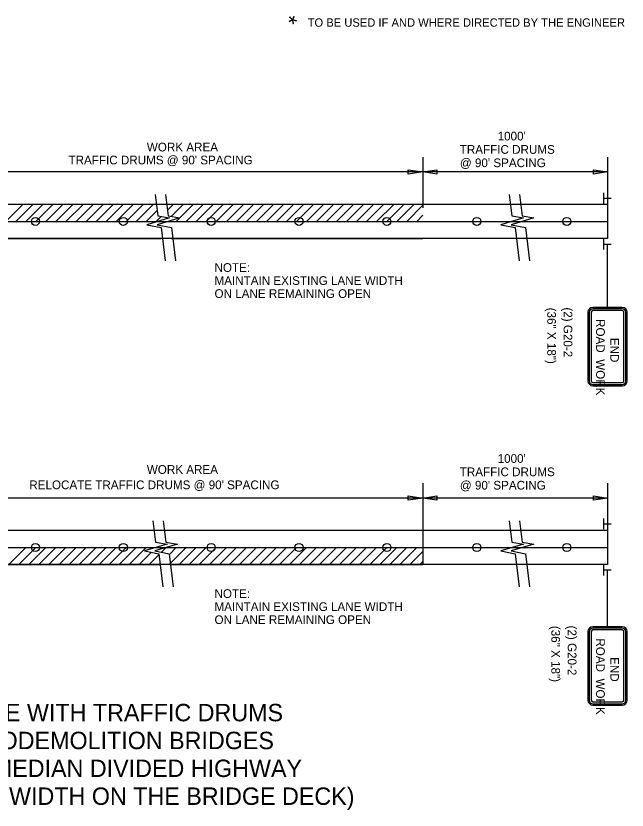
# Model space of a CAD drawing. Extents: x 1930579 to 1938222, y 596452 to 597761.
# Drawn here: x 1937236 to 1937657, y 596554 to 597101 of the extents above; entities that cross this region are included whole.
import ezdxf

# ---------------------------------------------------------------- set-up
doc = ezdxf.new("R2010")
doc.units = 0
for name, color, linetype in [('Default', 7, 'Continuous'), ('P_TC_Signs_Temporary', 7, 'Continuous'), ('R_Border', 7, 'Continuous')]:
    doc.layers.add(name, color=color, linetype=linetype)

msp = doc.modelspace()

# ---------------------------------------------------------------- linework, layer by layer
at = {"layer": 'Default'}
for p, q in [((1937516.16, 597003.98), (1937516.16, 596968.94)), ((1937643.39, 597003.98), (1937643.39, 596947.87)), ((1937506.1, 596992.19), (1937506.1, 596995.2)), ((1937506.1, 596995.2), (1937516.16, 596993.7)), ((1937516.16, 596993.7), (1937525.82, 596995.15)), ((1937525.82, 596995.15), (1937525.82, 596992.25)), ((1937633.73, 596992.25), (1937633.73, 596995.15)), ((1937633.73, 596995.15), (1937643.39, 596993.7)), ((1937516.16, 596993.7), (1937188.67, 596993.7)), ((1937516.16, 596993.7), (1937506.1, 596992.19)), ((1937525.82, 596992.25), (1937516.16, 596993.7)), ((1937643.39, 596993.7), (1937516.16, 596993.7)), ((1937643.39, 596993.7), (1937633.73, 596992.25)), ((1937640.73, 596979.4), (1937640.73, 596971.92)), ((1937640.84, 596975.68), (1937645.95, 596975.68)), ((1937643.39, 596971.31), (1936696.54, 596971.31)), ((1937228.83, 596959.59), (1937240.55, 596971.31)), ((1937235.73, 596959.59), (1937247.45, 596971.31)), ((1937242.64, 596959.59), (1937254.36, 596971.31)), ((1937249.54, 596959.59), (1937261.26, 596971.31)), ((1937256.45, 596959.59), (1937268.17, 596971.31)), ((1937263.35, 596959.59), (1937275.07, 596971.31)), ((1937270.26, 596959.59), (1937281.98, 596971.31)), ((1937277.16, 596959.59), (1937288.88, 596971.31)), ((1937284.07, 596959.59), (1937295.79, 596971.31)), ((1937290.97, 596959.59), (1937302.69, 596971.31)), ((1937297.88, 596959.59), (1937309.6, 596971.31)), ((1937304.79, 596959.59), (1937316.5, 596971.31)), ((1937311.69, 596959.59), (1937323.41, 596971.31)), ((1937318.6, 596959.59), (1937330.31, 596971.31)), ((1937325.5, 596959.59), (1937333.09, 596967.18)), ((1937340.18, 596967.37), (1937344.13, 596971.31)), ((1937342.74, 596963.02), (1937351.03, 596971.31)), ((1937348.61, 596961.98), (1937357.94, 596971.31)), ((1937353.12, 596959.59), (1937364.84, 596971.31)), ((1937360.03, 596959.59), (1937371.75, 596971.31)), ((1937366.93, 596959.59), (1937378.65, 596971.31)), ((1937373.84, 596959.59), (1937385.56, 596971.31)), ((1937380.74, 596959.59), (1937392.46, 596971.31)), ((1937387.65, 596959.59), (1937399.37, 596971.31)), ((1937394.55, 596959.59), (1937406.27, 596971.31)), ((1937401.46, 596959.59), (1937413.18, 596971.31)), ((1937408.37, 596959.59), (1937420.08, 596971.31)), ((1937415.27, 596959.59), (1937426.99, 596971.31)), ((1937422.18, 596959.59), (1937433.89, 596971.31)), ((1937429.08, 596959.59), (1937440.8, 596971.31)), ((1937435.99, 596959.59), (1937447.71, 596971.31)), ((1937442.89, 596959.59), (1937454.61, 596971.31)), ((1937449.8, 596959.59), (1937461.52, 596971.31)), ((1937456.7, 596959.59), (1937468.42, 596971.31)), ((1937463.61, 596959.59), (1937475.33, 596971.31)), ((1937470.51, 596959.59), (1937482.23, 596971.31)), ((1937477.42, 596959.59), (1937489.14, 596971.31)), ((1937484.32, 596959.59), (1937496.04, 596971.31)), ((1937491.23, 596959.59), (1937502.95, 596971.31)), ((1937498.13, 596959.59), (1937509.85, 596971.31)), ((1937505.04, 596959.59), (1937516.16, 596970.71)), ((1937332.41, 596959.59), (1937335.81, 596962.99)), ((1937346.22, 596959.59), (1937348.52, 596961.89)), ((1937511.95, 596959.59), (1937516.16, 596963.8)), ((1936696.54, 596959.59), (1937643.39, 596959.59)), ((1937643.39, 596947.87), (1936696.54, 596947.87)), ((1937188.46, 596947.87), (1937335.53, 596947.87)), ((1937343, 596947.87), (1937516.16, 596947.87)), ((1937640.73, 596947.64), (1937640.73, 596940.16)), ((1937640.84, 596943.92), (1937645.95, 596943.92)), ((1937516.16, 596779.28), (1937516.16, 596723.17)), ((1937516.16, 596779.28), (1937516.16, 596744.24)), ((1937643.39, 596779.28), (1937643.39, 596723.17)), ((1937506.1, 596767.49), (1937506.1, 596770.5)), ((1937506.1, 596770.5), (1937516.16, 596769)), ((1937516.16, 596769), (1937525.82, 596770.45)), ((1937525.82, 596770.45), (1937525.82, 596767.55)), ((1937633.73, 596767.55), (1937633.73, 596770.45)), ((1937633.73, 596770.45), (1937643.39, 596769)), ((1937516.16, 596769), (1937188.67, 596769)), ((1937516.16, 596769), (1937506.1, 596767.49)), ((1937525.82, 596767.55), (1937516.16, 596769)), ((1937643.39, 596769), (1937516.16, 596769)), ((1937643.39, 596769), (1937633.73, 596767.55)), ((1937640.73, 596754.94), (1937640.73, 596747.46)), ((1937640.84, 596751.22), (1937645.95, 596751.22)), ((1937643.39, 596746.61), (1936696.54, 596746.61)), ((1936696.54, 596734.89), (1937643.39, 596734.89)), ((1937230.92, 596723.17), (1937242.64, 596734.89)), ((1937237.82, 596723.17), (1937249.54, 596734.89)), ((1937244.73, 596723.17), (1937256.45, 596734.89)), ((1937251.63, 596723.17), (1937263.35, 596734.89)), ((1937258.54, 596723.17), (1937270.26, 596734.89)), ((1937265.45, 596723.17), (1937277.16, 596734.89)), ((1937272.35, 596723.17), (1937284.07, 596734.89)), ((1937279.26, 596723.17), (1937290.97, 596734.89)), ((1937286.16, 596723.17), (1937297.88, 596734.89)), ((1937293.07, 596723.17), (1937304.79, 596734.89)), ((1937299.97, 596723.17), (1937311.69, 596734.89)), ((1937306.88, 596723.17), (1937318.6, 596734.89)), ((1937313.78, 596723.17), (1937325.5, 596734.89)), ((1937336.07, 596731.64), (1937339.31, 596734.89)), ((1937341.4, 596723.17), (1937353.12, 596734.89)), ((1937341.5, 596730.17), (1937346.22, 596734.89)), ((1937348.31, 596723.17), (1937360.03, 596734.89)), ((1937355.21, 596723.17), (1937366.93, 596734.89)), ((1937362.12, 596723.17), (1937373.84, 596734.89)), ((1937369.03, 596723.17), (1937380.74, 596734.89)), ((1937375.93, 596723.17), (1937387.65, 596734.89)), ((1937382.84, 596723.17), (1937394.55, 596734.89)), ((1937389.74, 596723.17), (1937401.46, 596734.89)), ((1937396.65, 596723.17), (1937408.37, 596734.89)), ((1937403.55, 596723.17), (1937415.27, 596734.89)), ((1937410.46, 596723.17), (1937422.18, 596734.89)), ((1937417.36, 596723.17), (1937429.08, 596734.89)), ((1937424.27, 596723.17), (1937435.99, 596734.89)), ((1937431.17, 596723.17), (1937442.89, 596734.89)), ((1937438.08, 596723.17), (1937449.8, 596734.89)), ((1937444.98, 596723.17), (1937456.7, 596734.89)), ((1937451.89, 596723.17), (1937463.61, 596734.89)), ((1937458.79, 596723.17), (1937470.51, 596734.89)), ((1937465.7, 596723.17), (1937477.42, 596734.89)), ((1937472.61, 596723.17), (1937484.32, 596734.89)), ((1937479.51, 596723.17), (1937491.23, 596734.89)), ((1937486.42, 596723.17), (1937498.13, 596734.89)), ((1937493.32, 596723.17), (1937505.04, 596734.89)), ((1937500.23, 596723.17), (1937511.95, 596734.89)), ((1937507.13, 596723.17), (1937516.16, 596732.19)), ((1937320.69, 596723.17), (1937329.13, 596731.61)), ((1937327.59, 596723.17), (1937334.41, 596729.99)), ((1937643.39, 596723.17), (1936696.54, 596723.17)), ((1937188.46, 596723.17), (1937335.53, 596723.17)), ((1937334.5, 596723.17), (1937335.15, 596723.82)), ((1937343, 596723.17), (1937516.16, 596723.17)), ((1937514.04, 596723.17), (1937516.16, 596725.29)), ((1937640.73, 596723.18), (1937640.73, 596715.7)), ((1937640.84, 596719.46), (1937645.95, 596719.46))]:
    msp.add_line(p, q, dxfattribs=at)
for points in [[(1937331.74, 596978.04), (1937333.57, 596963.38), (1937341.63, 596961.96), (1937325.98, 596957.22), (1937335.94, 596955.32), (1937338.69, 596932.48)], [(1937338.85, 596978.04), (1937340.68, 596963.38), (1937348.74, 596961.96), (1937333.09, 596957.22), (1937343.05, 596955.32), (1937345.8, 596932.48)], [(1937575.66, 596978.04), (1937577.49, 596963.38), (1937585.55, 596961.96), (1937569.9, 596957.22), (1937579.86, 596955.32), (1937582.61, 596932.48)], [(1937582.77, 596978.04), (1937584.6, 596963.38), (1937592.66, 596961.96), (1937577.01, 596957.22), (1937586.97, 596955.32), (1937589.72, 596932.48)], [(1937330.13, 596753.34), (1937331.97, 596738.68), (1937340.03, 596737.26), (1937324.38, 596732.52), (1937334.34, 596730.62), (1937337.08, 596707.78)], [(1937337.25, 596753.34), (1937339.08, 596738.68), (1937347.14, 596737.26), (1937331.49, 596732.52), (1937341.45, 596730.62), (1937344.2, 596707.78)], [(1937575.66, 596753.34), (1937577.49, 596738.68), (1937585.55, 596737.26), (1937569.9, 596732.52), (1937579.86, 596730.62), (1937582.61, 596707.78)], [(1937582.77, 596753.34), (1937584.6, 596738.68), (1937592.66, 596737.26), (1937577.01, 596732.52), (1937586.97, 596730.62), (1937589.72, 596707.78)]]:
    msp.add_lwpolyline(points, dxfattribs=at)
for centre in [(1937249.21, 596959.59), (1937309.75, 596959.59), (1937370.29, 596959.59), (1937430.82, 596959.59), (1937491.36, 596959.59), (1937553.36, 596959.59), (1937615.36, 596959.59), (1937249.21, 596734.89), (1937309.75, 596734.89), (1937370.29, 596734.89), (1937430.82, 596734.89), (1937491.36, 596734.89), (1937553.36, 596734.89), (1937615.36, 596734.89)]:
    msp.add_circle(centre, 2.8, dxfattribs=at)
at = {"layer": 'P_TC_Signs_Temporary'}
for p, q in [((1937629.89, 596896.98), (1937629.89, 596849.73)), ((1937630.83, 596896.98), (1937630.83, 596849.73)), ((1937632.14, 596896.98), (1937632.14, 596849.73)), ((1937653.52, 596900.35), (1937633.27, 596900.35)), ((1937653.52, 596899.42), (1937633.27, 596899.42)), ((1937653.52, 596898.1), (1937633.27, 596898.1)), ((1937654.64, 596849.73), (1937654.64, 596896.98)), ((1937655.96, 596849.73), (1937655.96, 596896.98)), ((1937656.89, 596849.73), (1937656.89, 596896.98)), ((1937633.27, 596848.6), (1937653.52, 596848.6)), ((1937633.27, 596847.29), (1937653.52, 596847.29)), ((1937633.27, 596846.35), (1937653.52, 596846.35)), ((1937653.52, 596680.33), (1937633.27, 596680.33)), ((1937653.52, 596679.39), (1937633.27, 596679.39)), ((1937653.52, 596678.08), (1937633.27, 596678.08)), ((1937629.89, 596676.95), (1937629.89, 596629.7)), ((1937630.83, 596676.95), (1937630.83, 596629.7)), ((1937632.14, 596676.95), (1937632.14, 596629.7)), ((1937654.64, 596629.7), (1937654.64, 596676.95)), ((1937655.96, 596629.7), (1937655.96, 596676.95)), ((1937656.89, 596629.7), (1937656.89, 596676.95)), ((1937633.27, 596628.58), (1937653.52, 596628.58)), ((1937633.27, 596627.26), (1937653.52, 596627.26)), ((1937633.27, 596626.33), (1937653.52, 596626.33))]:
    msp.add_line(p, q, dxfattribs=at)
for centre, radius, start, end in [((1937633.27, 596896.98), 3.37, 90, 180), ((1937633.27, 596896.98), 2.44, 90, 180), ((1937633.27, 596896.98), 1.13, 90, 180), ((1937653.52, 596896.98), 3.37, 360, 90), ((1937653.52, 596896.98), 2.44, 360, 90), ((1937653.52, 596896.98), 1.13, 360, 90), ((1937633.27, 596849.73), 3.37, 180, 270), ((1937633.27, 596849.73), 2.44, 180, 270), ((1937633.27, 596849.73), 1.13, 180, 270), ((1937653.52, 596849.73), 2.44, 270, 360), ((1937653.52, 596849.73), 1.13, 270, 360), ((1937653.52, 596849.73), 3.38, 270, 360), ((1937633.27, 596676.95), 3.37, 90, 180), ((1937633.27, 596676.95), 2.44, 90, 180), ((1937633.27, 596676.95), 1.13, 90, 180), ((1937653.52, 596676.95), 3.37, 360, 90), ((1937653.52, 596676.95), 2.44, 360, 90), ((1937653.52, 596676.95), 1.13, 360, 90), ((1937633.27, 596629.7), 3.37, 180, 270), ((1937633.27, 596629.7), 2.44, 180, 270), ((1937633.27, 596629.7), 1.13, 180, 270), ((1937653.52, 596629.7), 2.44, 270, 360), ((1937653.52, 596629.7), 1.13, 270, 360), ((1937653.52, 596629.7), 3.38, 270, 360)]:
    msp.add_arc(centre, radius, start, end, dxfattribs=at)
at = {"layer": 'R_Border'}
for p, q in [((1937643.39, 596900.35), (1937643.39, 596943.92)), ((1937643.39, 596680.33), (1937643.39, 596719.46))]:
    msp.add_line(p, q, dxfattribs=at)

# ---------------------------------------------------------------- texts
at = {"layer": 'Default'}
for s, height, p in [("1000'", 6, (1937567.68, 597015.4)), ('WORK AREA', 6, (1937325.96, 597007.82)), ('TRAFFIC DRUMS ', 6, (1937541.56, 597006.2)), ("TRAFFIC DRUMS @ 90' SPACING", 6, (1937271.98, 596998.9)), ("@ 90' SPACING", 6, (1937541.66, 596996.99)), ("1000'", 6, (1937567.68, 596793.22)), ('WORK AREA', 6, (1937325.95, 596785.65)), ('TRAFFIC DRUMS ', 6, (1937541.56, 596784.03)), ("RELOCATE TRAFFIC DRUMS @ 90' SPACING", 6, (1937244.98, 596775.09)), ("@ 90' SPACING", 6, (1937541.66, 596774.81)), ('LANE CLOSURE WITH TRAFFIC DRUMS', 12, (1937114.93, 596615.15)), ('FOR HYDRODEMOLITION BRIDGES ', 12, (1937140.73, 596595.95)), ('4 LANE GRASS MEDIAN DIVIDED HIGHWAY', 12, (1937099.44, 596576.75)), ('(28\'-0" CLEAR ROADWAY WIDTH ON THE BRIDGE DECK)', 12, (1937035, 596557.55))]:
    msp.add_text(s, height=height, rotation=360, dxfattribs=at).set_placement(p)
at = {"layer": 'P_TC_Signs_Temporary'}
for s, p in [('ROAD  WORK', (1937635.52, 596892.31)), ('END', (1937645.27, 596879.38)), ('ROAD  WORK', (1937635.52, 596672.29)), ('END', (1937645.27, 596659.36))]:
    msp.add_text(s, height=6, rotation=270, dxfattribs=at).set_placement(p)
at = {"layer": 'R_Border'}
for s, height, rotation, p in [('*', 11.52, 45, (1937430.21, 597090.36)), ('TO BE USED IF AND WHERE DIRECTED BY THE ENGINEER', 5.76, 360, (1937436.77, 597093.75)), ('NOTE:', 6, 360, (1937372.6, 596924.82)), ('MAINTAIN EXISTING LANE WIDTH', 6, 360, (1937372.6, 596915.84)), ('ON LANE REMAINING OPEN', 6, 360, (1937372.6, 596906.86)), ('(36" X 18")', 6, 270, (1937601.85, 596900.15)), ('(2) G20-2', 6, 270, (1937613.15, 596900.35)), ('NOTE:', 6, 360, (1937372.6, 596700.12)), ('MAINTAIN EXISTING LANE WIDTH', 6, 360, (1937372.6, 596691.14)), ('ON LANE REMAINING OPEN', 6, 360, (1937372.6, 596682.16)), ('(36" X 18")', 6, 270, (1937604.68, 596680.9)), ('(2) G20-2', 6, 270, (1937615.99, 596681.1))]:
    msp.add_text(s, height=height, rotation=rotation, dxfattribs=at).set_placement(p)

doc.saveas('drawing.dxf')
